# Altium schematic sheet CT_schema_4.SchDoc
size 316 x 185 mm
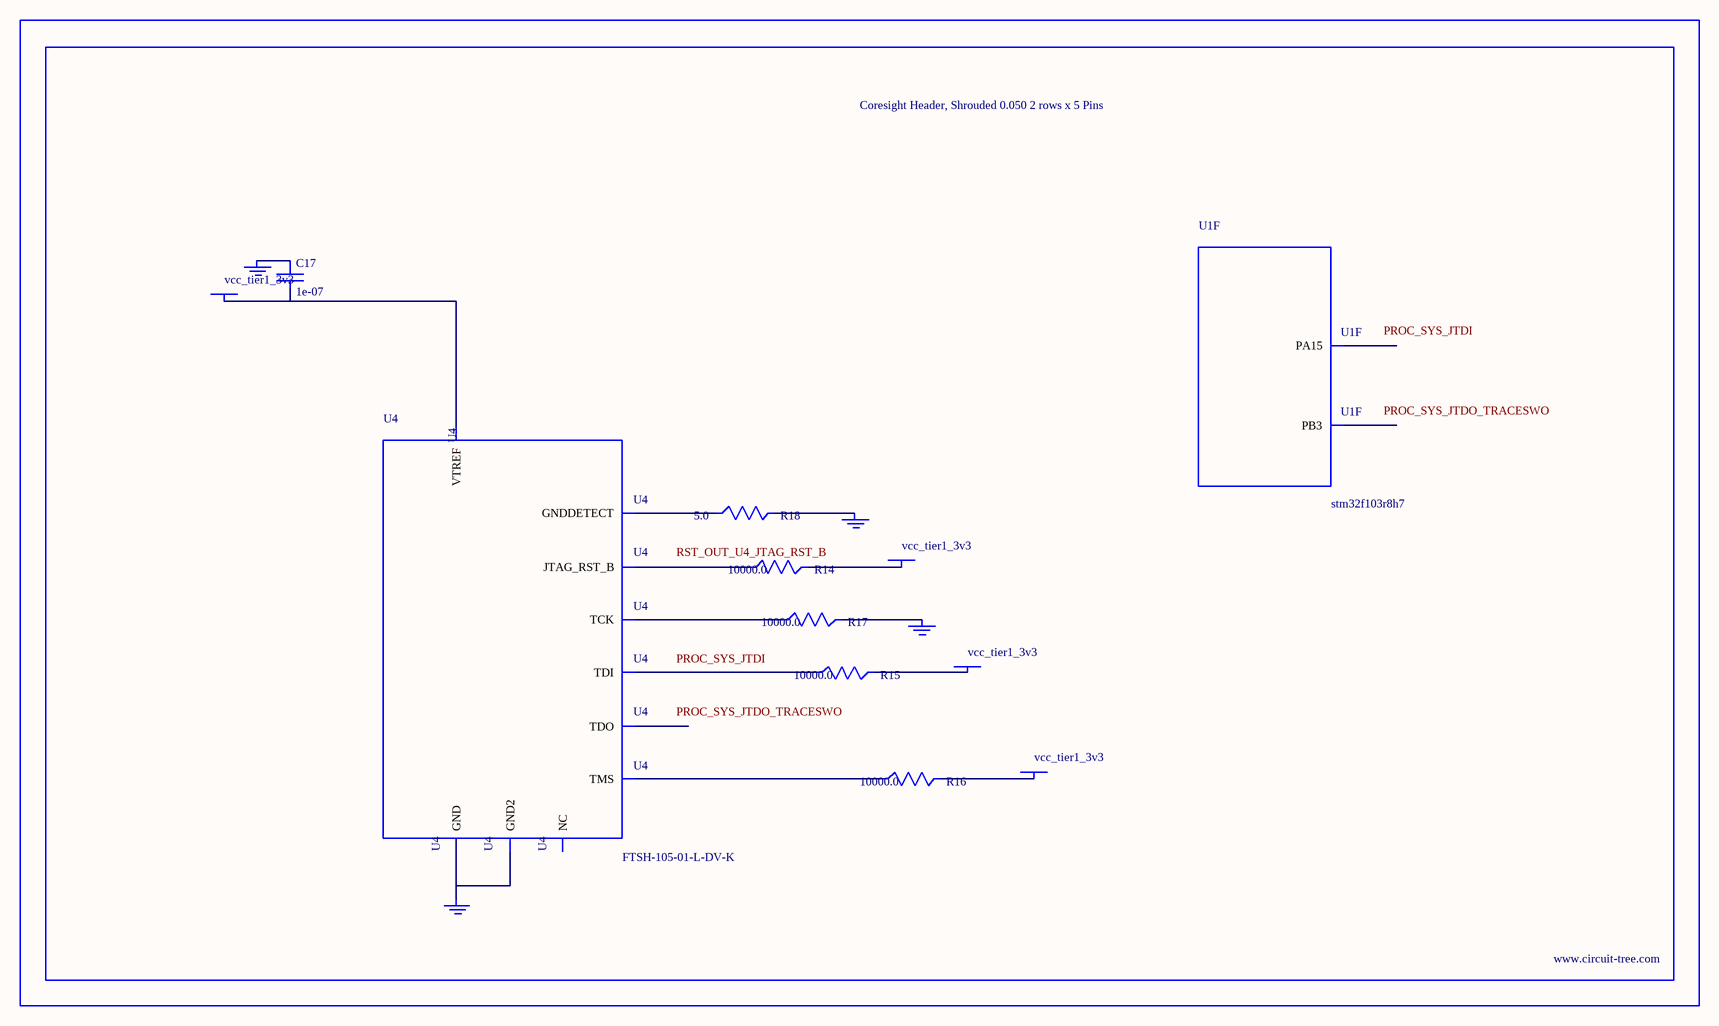
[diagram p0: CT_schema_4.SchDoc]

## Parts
BORDER3  (no value)
C17  1e-07  [C0402]
GND_INSTANCE_3_0  (no value)
GND_INSTANCE_3_1  (no value)
GND_INSTANCE_3_2  (no value)
GND_INSTANCE_3_3  (no value)
POWER_INSTANCE_3_0  vcc_tier1_3v3
POWER_INSTANCE_3_1  vcc_tier1_3v3
POWER_INSTANCE_3_2  vcc_tier1_3v3
POWER_INSTANCE_3_3  vcc_tier1_3v3
R14  10000.0  [R0603]
R15  10000.0  [R0603]
R16  10000.0  [R0603]
R17  10000.0  [R0603]
R18  5.0  [R0603]
U1  stm32f103r8h7  [TFBGA64]  (part F of 7)
U4  FTSH-105-01-L-DV-K  [SAMTEC_FTSH-105-01-L-DV-K]

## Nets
NetC17_1: C17.1 GND_INSTANCE_3_0.0(GND)
NetC17_2: C17.2 POWER_INSTANCE_3_0.0(PWR) U4.1(VTREF)
NetGND_INSTANCE_3_1_0: GND_INSTANCE_3_1.0(GND) R17.2
NetGND_INSTANCE_3_2_0: GND_INSTANCE_3_2.0(GND) R18.2
NetGND_INSTANCE_3_3_0: GND_INSTANCE_3_3.0(GND) U4.3(GND) U4.5(GND2)
NetPOWER_INSTANCE_3_1_0: POWER_INSTANCE_3_1.0(PWR) R16.2
NetPOWER_INSTANCE_3_2_0: POWER_INSTANCE_3_2.0(PWR) R15.2
NetPOWER_INSTANCE_3_3_0: POWER_INSTANCE_3_3.0(PWR) R14.2
NetR14_1: R14.1 U4.10(JTAG_RST_B)
NetR15_1: R15.1 U4.8(TDI)
NetR16_1: R16.1 U4.2(TMS)
NetR17_1: R17.1 U4.4(TCK)
NetR18_1: R18.1 U4.9(GNDDETECT)

Not connected (* = marked no-connect by the designer): U1 A5(PB3) A6(PA15); U4 6(TDO) 7(NC)

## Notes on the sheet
- Labels drawn without touching a wire or pin: PROC_SYS_JTDI, PROC_SYS_JTDO_TRACESWO, RST_OUT_U4_JTAG_RST_B

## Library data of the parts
BORDER3 = BORDER_PAGE3
C17 = C0402C104K3RACTU
GND_INSTANCE_3_0-GND_INSTANCE_3_3 = GND
POWER_INSTANCE_3_0-POWER_INSTANCE_3_3 = PWR
R14-R17 = RC0603JR-0710KL
R18 = ERJ-3GEYJ5R1V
